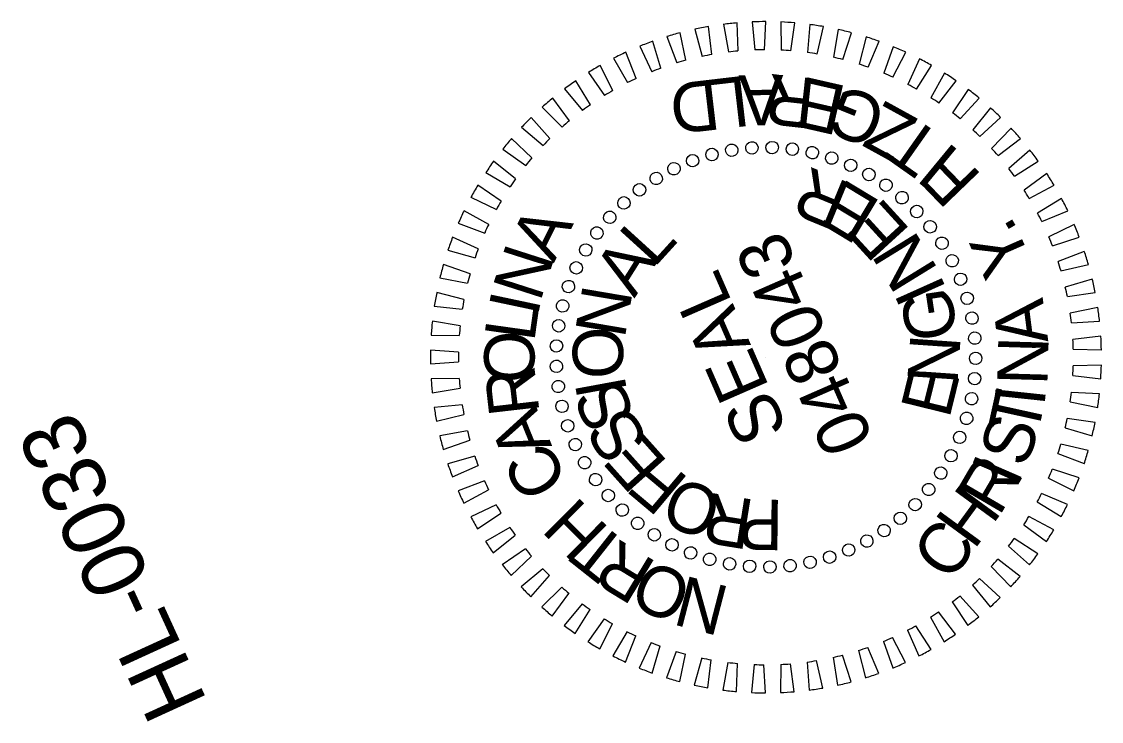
# Model space of a CAD drawing. Extents: x 2047210 to 2048779, y 758833 to 761037.
# Drawn here: x 2047247.5 to 2047376.2, y 760470.6 to 760554 of the extents above; entities that cross this region are included whole.
import ezdxf

# ---------------------------------------------------------------- set-up
doc = ezdxf.new("R2010")
doc.units = 0
doc.layers.add('Sheet Data Field CELL', color=7, linetype='Continuous')
doc.layers.add('Sheet PE Seal Cell', color=7, linetype='Continuous')

msp = doc.modelspace()

# ---------------------------------------------------------------- linework, layer by layer
at = {"layer": 'Sheet PE Seal Cell'}
for p, q in [((2047329.74, 760550.11), (2047329.34, 760553.44)), ((2047331.12, 760553.71), (2047331.72, 760550.41)), ((2047332.87, 760550.53), (2047332.76, 760553.88)), ((2047334.55, 760554), (2047334.87, 760550.66)), ((2047336.02, 760550.68), (2047336.2, 760554.03)), ((2047337.99, 760553.99), (2047338.02, 760550.64)), ((2047339.17, 760550.56), (2047339.63, 760553.88)), ((2047341.42, 760553.69), (2047341.16, 760550.34)), ((2047342.3, 760550.17), (2047343.05, 760553.44)), ((2047324.4, 760552.25), (2047325.56, 760549.1)), ((2047326.66, 760549.42), (2047325.98, 760552.71)), ((2047327.73, 760553.12), (2047328.61, 760549.89)), ((2047344.81, 760553.09), (2047344.26, 760549.78)), ((2047345.38, 760549.51), (2047346.41, 760552.71)), ((2047348.13, 760552.21), (2047347.31, 760548.96)), ((2047321.15, 760551.09), (2047322.58, 760548.06)), ((2047323.66, 760548.47), (2047322.7, 760551.68)), ((2047348.4, 760548.59), (2047349.7, 760551.69)), ((2047351.37, 760551.04), (2047350.27, 760547.87)), ((2047318.02, 760549.66), (2047319.71, 760546.76)), ((2047320.74, 760547.26), (2047319.51, 760550.38)), ((2047351.32, 760547.42), (2047352.88, 760550.39)), ((2047354.5, 760549.6), (2047353.12, 760546.54)), ((2047317.94, 760545.81), (2047316.45, 760548.81)), ((2047354.14, 760545.99), (2047355.95, 760548.82)), ((2047315.28, 760544.12), (2047313.53, 760546.99)), ((2047315.03, 760547.97), (2047316.95, 760545.22)), ((2047357.49, 760547.9), (2047355.86, 760544.96)), ((2047356.82, 760544.33), (2047358.86, 760546.99)), ((2047312.19, 760546.02), (2047314.34, 760543.45)), ((2047360.32, 760545.94), (2047358.44, 760543.16)), ((2047312.77, 760542.21), (2047310.78, 760544.92)), ((2047359.35, 760542.45), (2047361.61, 760544.92)), ((2047309.53, 760543.84), (2047311.9, 760541.47)), ((2047362.97, 760543.75), (2047360.86, 760541.14)), ((2047310.43, 760540.1), (2047308.22, 760542.62)), ((2047361.7, 760540.35), (2047364.18, 760542.62)), ((2047307.06, 760541.44), (2047309.63, 760539.28)), ((2047365.43, 760541.34), (2047363.1, 760538.92)), ((2047308.29, 760537.78), (2047305.86, 760540.11)), ((2047363.87, 760538.06), (2047366.53, 760540.11)), ((2047304.82, 760538.83), (2047307.56, 760536.9)), ((2047367.67, 760538.72), (2047365.14, 760536.51)), ((2047306.35, 760535.3), (2047303.74, 760537.4)), ((2047365.83, 760535.6), (2047368.66, 760537.41)), ((2047302.8, 760536.04), (2047305.7, 760534.35)), ((2047369.67, 760535.93), (2047366.97, 760533.94)), ((2047304.63, 760532.65), (2047301.85, 760534.52)), ((2047367.58, 760532.97), (2047370.55, 760534.53)), ((2047301.03, 760533.09), (2047304.06, 760531.65)), ((2047371.43, 760532.97), (2047368.57, 760531.22)), ((2047303.15, 760529.87), (2047300.21, 760531.5)), ((2047369.09, 760530.2), (2047372.18, 760531.5)), ((2047299.52, 760530), (2047302.67, 760528.83)), ((2047372.93, 760529.87), (2047369.92, 760528.38)), ((2047301.91, 760526.97), (2047298.84, 760528.34)), ((2047370.36, 760527.31), (2047373.55, 760528.34)), ((2047298.29, 760526.78), (2047301.52, 760525.89)), ((2047374.15, 760526.65), (2047371.03, 760525.43)), ((2047300.92, 760523.97), (2047297.75, 760525.07)), ((2047371.37, 760524.33), (2047374.64, 760525.08)), ((2047297.33, 760523.48), (2047300.63, 760522.86)), ((2047375.1, 760523.34), (2047371.88, 760522.39)), ((2047300.2, 760520.91), (2047296.95, 760521.73)), ((2047372.13, 760521.27), (2047375.45, 760521.73)), ((2047296.66, 760520.1), (2047300, 760519.77)), ((2047375.76, 760519.97), (2047372.47, 760519.29)), ((2047299.74, 760517.79), (2047296.43, 760518.32)), ((2047372.62, 760518.15), (2047375.97, 760518.33)), ((2047296.29, 760516.68), (2047299.64, 760516.64)), ((2047376.12, 760516.54), (2047372.79, 760516.15)), ((2047299.55, 760514.64), (2047296.21, 760514.89)), ((2047372.84, 760515), (2047376.19, 760514.9)), ((2047296.21, 760513.24), (2047299.55, 760513.49)), ((2047336.2, 760514.03), (2047336.2, 760514.03)), ((2047376.19, 760513.1), (2047372.83, 760513)), ((2047299.64, 760511.48), (2047296.28, 760511.45)), ((2047372.78, 760511.85), (2047376.12, 760511.45)), ((2047296.42, 760509.81), (2047299.74, 760510.34)), ((2047375.96, 760509.67), (2047372.61, 760509.85)), ((2047299.99, 760508.35), (2047296.65, 760508.03)), ((2047372.46, 760508.71), (2047375.75, 760508.03)), ((2047296.93, 760506.4), (2047300.19, 760507.22)), ((2047371.87, 760505.62), (2047375.08, 760504.65)), ((2047375.44, 760506.27), (2047372.12, 760506.74)), ((2047300.61, 760505.26), (2047297.31, 760504.65)), ((2047297.73, 760503.05), (2047300.91, 760504.15)), ((2047374.62, 760502.92), (2047371.36, 760503.68)), ((2047301.5, 760502.23), (2047298.27, 760501.34)), ((2047371.01, 760502.58), (2047374.13, 760501.35)), ((2047298.82, 760499.79), (2047301.89, 760501.15)), ((2047373.53, 760499.66), (2047370.34, 760500.69)), ((2047302.64, 760499.29), (2047299.5, 760498.13)), ((2047369.9, 760499.63), (2047372.9, 760498.13)), ((2047300.18, 760496.63), (2047303.12, 760498.25)), ((2047368.54, 760496.79), (2047371.4, 760495.04)), ((2047372.15, 760496.5), (2047369.06, 760497.81)), ((2047304.03, 760496.46), (2047301, 760495.03)), ((2047301.81, 760493.6), (2047304.6, 760495.46)), ((2047366.94, 760494.07), (2047369.64, 760492.08)), ((2047370.51, 760493.48), (2047367.55, 760495.04)), ((2047305.66, 760493.76), (2047302.76, 760492.08)), ((2047303.7, 760490.72), (2047306.31, 760492.82)), ((2047365.11, 760491.5), (2047367.63, 760489.29)), ((2047368.62, 760490.6), (2047365.8, 760492.42)), ((2047307.52, 760491.21), (2047304.77, 760489.28)), ((2047305.82, 760488.01), (2047308.25, 760490.33)), ((2047363.06, 760489.1), (2047365.38, 760486.68)), ((2047366.49, 760487.9), (2047363.83, 760489.96)), ((2047309.59, 760488.83), (2047307.02, 760486.67)), ((2047308.17, 760485.49), (2047310.39, 760488.01)), ((2047364.13, 760485.4), (2047361.66, 760487.67)), ((2047311.85, 760486.64), (2047309.48, 760484.27)), ((2047360.82, 760486.88), (2047362.92, 760484.27)), ((2047310.73, 760483.19), (2047312.72, 760485.89)), ((2047361.56, 760483.1), (2047359.3, 760485.58)), ((2047314.3, 760484.65), (2047312.14, 760482.08)), ((2047313.47, 760481.11), (2047315.23, 760483.97)), ((2047358.39, 760484.87), (2047360.27, 760482.08)), ((2047316.9, 760482.87), (2047314.97, 760480.13)), ((2047355.81, 760483.07), (2047357.43, 760480.13)), ((2047358.81, 760481.04), (2047356.77, 760483.7)), ((2047316.39, 760479.28), (2047317.89, 760482.28)), ((2047319.65, 760481.33), (2047317.96, 760478.43)), ((2047353.07, 760481.5), (2047354.44, 760478.43)), ((2047355.89, 760479.21), (2047354.08, 760482.04)), ((2047319.45, 760477.71), (2047320.69, 760480.83)), ((2047322.53, 760480.03), (2047321.09, 760476.99)), ((2047350.21, 760480.17), (2047351.31, 760477)), ((2047352.82, 760477.65), (2047351.27, 760480.62)), ((2047322.63, 760476.4), (2047323.6, 760479.62)), ((2047325.5, 760478.98), (2047324.33, 760475.83)), ((2047325.92, 760475.38), (2047326.6, 760478.66)), ((2047347.25, 760479.09), (2047348.07, 760475.83)), ((2047349.64, 760476.36), (2047348.34, 760479.45)), ((2047328.55, 760478.19), (2047327.66, 760474.95)), ((2047329.28, 760474.64), (2047329.68, 760477.97)), ((2047331.66, 760477.66), (2047331.05, 760474.36)), ((2047332.69, 760474.19), (2047332.81, 760477.54)), ((2047334.81, 760477.41), (2047334.48, 760474.07)), ((2047336.13, 760474.03), (2047335.95, 760477.38)), ((2047337.96, 760477.42), (2047337.92, 760474.07)), ((2047339.57, 760474.17), (2047339.11, 760477.5)), ((2047341.1, 760477.71), (2047341.35, 760474.37)), ((2047342.98, 760474.61), (2047342.24, 760477.88)), ((2047344.2, 760478.27), (2047344.74, 760474.96)), ((2047346.35, 760475.34), (2047345.32, 760478.54))]:
    msp.add_line(p, q, dxfattribs=at)
for radius, start, end in [(40, 99.8668, 102.2304), (40, 94.9353, 97.2989), (40, 90.0038, 92.3674), (40, 85.0722, 87.4359), (40, 80.1407, 82.5044), (40, 104.7983, 107.1619), (40, 75.2092, 77.5729), (40, 70.2777, 72.6413), (40, 109.7298, 112.0934), (36.65, 90.2866, 92.0845), (40, 65.3462, 67.7098), (40, 114.6613, 117.0249), (36.65, 105.0811, 106.879), (36.65, 100.1496, 101.9475), (36.65, 95.2181, 97.016), (36.65, 85.3551, 87.153), (36.65, 80.4236, 82.2215), (36.65, 75.4921, 77.29), (40, 60.4147, 62.7783), (40, 119.5928, 121.9564), (36.65, 110.0126, 111.8105), (36.65, 70.5606, 72.3585), (40, 124.5243, 126.8879), (36.65, 114.9442, 116.742), (36.65, 65.6291, 67.427), (40, 55.4832, 57.8468), (36.65, 119.8757, 121.6736), (36.65, 60.6976, 62.4955), (40, 50.5517, 52.9153), (40, 129.4558, 131.8194), (36.65, 55.7661, 57.564), (36.65, 124.8072, 126.6051), (36.65, 50.8346, 52.6325), (40, 45.6202, 47.9838), (40, 134.3873, 136.7509), (36.65, 129.7387, 131.5366), (36.65, 45.9031, 47.701), (40, 40.6887, 43.0523), (40, 139.3188, 141.6824), (36.65, 134.6702, 136.4681), (36.65, 139.6017, 141.3996), (36.65, 40.9716, 42.7694), (40, 35.7572, 38.1208), (40, 144.2503, 146.614), (36.65, 36.04, 37.8379), (36.65, 144.5332, 146.3311), (40, 30.8257, 33.1893), (40, 149.1818, 151.5455), (36.65, 31.1085, 32.9064), (36.65, 149.4647, 151.2626), (40, 25.8942, 28.2578), (40, 154.1133, 156.477), (36.65, 26.177, 27.9749), (36.65, 154.3962, 156.1941), (40, 20.9627, 23.3263), (40, 159.0449, 161.4085), (36.65, 21.2455, 23.0434), (36.65, 159.3277, 161.1256), (40, 16.0312, 18.3948), (40, 163.9764, 166.34), (36.65, 16.314, 18.1119), (36.65, 164.2592, 166.0571), (36.65, 11.3825, 13.1804), (40, 11.0996, 13.4633), (40, 168.9079, 171.2715), (36.65, 169.1907, 170.9886), (40, 6.1681, 8.5318), (36.65, 6.451, 8.2489), (40, 173.8394, 176.203), (36.65, 174.1222, 175.9201), (36.65, 1.5195, 3.3174), (40, 1.2366, 3.6003), (40, 178.7709, 181.1345), (36.65, 179.0537, 180.8516), (36.65, 356.588, 358.3859), (40, 356.3051, 358.6687), (40, 183.7024, 186.066), (36.65, 183.9852, 185.7831), (36.65, 351.6565, 353.4544), (40, 351.3736, 353.7372), (36.65, 188.9168, 190.7147), (40, 188.6339, 190.9975), (36.65, 346.725, 348.5229), (40, 346.4421, 348.8057), (40, 193.5654, 195.929), (36.65, 193.8483, 195.6462), (36.65, 341.7935, 343.5914), (36.65, 198.7798, 200.5777), (40, 341.5106, 343.8742), (40, 198.4969, 200.8605), (36.65, 336.862, 338.6599), (36.65, 203.7113, 205.5092), (40, 336.5791, 338.9427), (40, 203.4284, 205.792), (36.65, 331.9305, 333.7283), (36.65, 208.6428, 210.4407), (40, 331.6476, 334.0112), (40, 208.3599, 210.7235), (36.65, 326.9989, 328.7968), (36.65, 213.5743, 215.3722), (40, 326.7161, 329.0797), (40, 213.2914, 215.655), (36.65, 322.0674, 323.8653), (36.65, 218.5058, 220.3037), (40, 321.7846, 324.1482), (40, 218.2229, 220.5866), (36.65, 317.1359, 318.9338), (36.65, 223.4373, 225.2352), (36.65, 312.2044, 314.0023), (40, 316.8531, 319.2167), (40, 223.1544, 225.5181), (36.65, 228.3688, 230.1667), (36.65, 307.2729, 309.0708), (40, 311.9216, 314.2852), (40, 228.0859, 230.4496), (36.65, 233.3003, 235.0982), (36.65, 238.2318, 240.0297), (36.65, 302.3414, 304.1393), (40, 306.9901, 309.3537), (40, 233.0175, 235.3811), (36.65, 243.1633, 244.9612), (36.65, 297.4099, 299.2078), (40, 237.949, 240.3126), (36.65, 248.0948, 249.8927), (36.65, 292.4784, 294.2763), (40, 302.0586, 304.4222), (36.65, 253.0263, 254.8242), (36.65, 287.5469, 289.3448), (40, 297.127, 299.4907), (40, 242.8805, 245.2441), (36.65, 257.9579, 259.7557), (36.65, 262.8894, 264.6873), (36.65, 267.8209, 269.6188), (36.65, 272.7524, 274.5503), (36.65, 277.6839, 279.4818), (36.65, 282.6154, 284.4133), (40, 292.1955, 294.5592), (40, 247.812, 250.1756), (40, 287.264, 289.6276), (40, 252.7435, 255.1071), (40, 257.675, 260.0386), (40, 282.3325, 284.6961), (40, 262.6065, 264.9701), (40, 267.538, 269.9016), (40, 272.4695, 274.8331), (40, 277.401, 279.7646)]:
    msp.add_arc((2047336.2, 760514.03), radius, start, end, dxfattribs=at)
for centre, major_axis in [((2047332.12, 760538.7), (-0.172, 0.722)), ((2047334.52, 760538.98), (-0.101, 0.735)), ((2047336.94, 760539.02), (-0.03, 0.742)), ((2047339.35, 760538.83), (0.042, 0.741)), ((2047341.73, 760538.41), (0.113, 0.734)), ((2047327.46, 760537.46), (-0.307, 0.676)), ((2047329.76, 760538.19), (-0.241, 0.702)), ((2047344.05, 760537.77), (0.184, 0.719)), ((2047325.24, 760536.5), (-0.371, 0.643)), ((2047346.31, 760536.9), (0.252, 0.698)), ((2047348.47, 760535.81), (0.318, 0.671)), ((2047323.12, 760535.34), (-0.431, 0.604)), ((2047350.51, 760534.53), (0.382, 0.637)), ((2047321.13, 760533.98), (-0.488, 0.56)), ((2047319.27, 760532.43), (-0.539, 0.51)), ((2047352.42, 760533.05), (0.441, 0.597)), ((2047317.58, 760530.71), (-0.586, 0.456)), ((2047354.18, 760531.4), (0.497, 0.552)), ((2047355.78, 760529.58), (0.548, 0.501)), ((2047316.05, 760528.84), (-0.627, 0.397)), ((2047314.72, 760526.82), (-0.663, 0.334)), ((2047357.19, 760527.62), (0.593, 0.446)), ((2047358.4, 760525.53), (0.634, 0.387)), ((2047313.58, 760524.69), (-0.692, 0.269)), ((2047359.4, 760523.33), (0.668, 0.324)), ((2047312.66, 760522.46), (-0.715, 0.201)), ((2047360.19, 760521.05), (0.696, 0.258)), ((2047311.96, 760520.15), (-0.731, 0.131)), ((2047311.48, 760517.78), (-0.74, 0.06)), ((2047360.76, 760518.7), (0.718, 0.189)), ((2047311.23, 760515.38), (-0.742, -0.012)), ((2047361.09, 760516.31), (0.733, 0.119)), ((2047361.2, 760513.9), (0.741, 0.048)), ((2047311.22, 760512.96), (-0.738, -0.083)), ((2047361.07, 760511.48), (0.742, -0.024)), ((2047311.44, 760510.55), (-0.726, -0.154)), ((2047360.71, 760509.09), (0.736, -0.095)), ((2047311.89, 760508.18), (-0.708, -0.224)), ((2047360.12, 760506.75), (0.724, -0.166)), ((2047312.57, 760505.86), (-0.683, -0.291)), ((2047313.47, 760503.62), (-0.652, -0.355)), ((2047359.3, 760504.48), (0.704, -0.235)), ((2047358.27, 760502.29), (0.678, -0.302)), ((2047314.58, 760501.48), (-0.614, -0.417)), ((2047357.04, 760500.22), (0.646, -0.366)), ((2047315.89, 760499.45), (-0.571, -0.474)), ((2047317.4, 760497.56), (-0.523, -0.527)), ((2047355.6, 760498.27), (0.607, -0.427)), ((2047319.07, 760495.82), (-0.47, -0.575)), ((2047353.99, 760496.47), (0.563, -0.483)), ((2047352.22, 760494.84), (0.514, -0.535)), ((2047320.91, 760494.25), (-0.412, -0.618)), ((2047350.29, 760493.38), (0.46, -0.583)), ((2047322.89, 760492.87), (-0.35, -0.654)), ((2047348.23, 760492.12), (0.402, -0.624)), ((2047325, 760491.68), (-0.286, -0.685)), ((2047327.21, 760490.71), (-0.218, -0.71)), ((2047346.06, 760491.06), (0.34, -0.66)), ((2047329.5, 760489.95), (-0.149, -0.727)), ((2047331.86, 760489.41), (-0.078, -0.738)), ((2047341.46, 760489.59), (0.206, -0.713)), ((2047343.79, 760490.21), (0.274, -0.69)), ((2047334.25, 760489.11), (-0.006, -0.742)), ((2047336.67, 760489.04), (0.066, -0.739)), ((2047339.08, 760489.2), (0.137, -0.73))]:
    msp.add_ellipse(centre, major_axis=major_axis, ratio=0.999708, dxfattribs=at)

# ---------------------------------------------------------------- texts
at = {"layer": 'Sheet Data Field CELL'}
msp.add_text('HL-0033', height=7.5, rotation=114.5739, dxfattribs=at).set_placement((2047269.65, 760473))
at = {"layer": 'Sheet PE Seal Cell'}
for s, height, rotation, p in [('D', 6, 186.6623, (2047330.24, 760547.19)), ('L', 6, 186.6623, (2047333.74, 760547.6)), ('A', 6, 180.5461, (2047338.28, 760547.68)), ('R', 6, 173.7238, (2047342.27, 760547.2)), ('E', 6, 167.1492, (2047346.02, 760546.28)), ('G', 6, 158.1586, (2047350.94, 760544.35)), ('Z', 6, 151.1917, (2047354.51, 760542.34)), ('T', 6, 144.8236, (2047357.54, 760540.13)), ('I', 6, 140.4585, (2047359.46, 760538.43)), ('R', 6, 157.6079, (2047346.58, 760534.63)), ('F', 6, 133.9459, (2047362.08, 760535.63)), ('E', 6, 148.8549, (2047350.08, 760532.48)), ('E', 6, 132.4512, (2047353.56, 760529.11)), ('A', 6, 63.2869, (2047310.91, 760525.21)), ('.', 6, 120.7864, (2047366.32, 760529.17)), ('L', 6, 47.6989, (2047322.81, 760524.58)), ('N', 6, 121.602, (2047356.81, 760524.42)), ('048043', 6.185, 113.6102, (2047349.12, 760504.15)), ('Y', 6, 113.6749, (2047367.96, 760525.32)), ('N', 6, 72.2172, (2047309.27, 760520.51)), ('A', 6, 57.832, (2047320.52, 760521.01)), ('SEAL', 6.184, 113.6102, (2047338.85, 760505.38)), ('I', 6, 114.1525, (2047357.77, 760522.09)), ('I', 6, 78.0537, (2047308.98, 760518.8)), ('N', 6, 80.3523, (2047319.35, 760516.15)), ('G', 6, 98.5678, (2047359.07, 760516.47)), ('A', 6, 97.3045, (2047369.86, 760515.91)), ('L', 6, 82.0413, (2047308.57, 760515.76)), ('O', 6, 92.0658, (2047319.28, 760511.55)), ('O', 6, 89.2416, (2047308.57, 760510.91)), ('N', 6, 86.0381, (2047359.02, 760510.71)), ('N', 6, 88.3139, (2047369.74, 760510.63)), ('R', 6, 96.5309, (2047309.22, 760507.41)), ('E', 6, 76.1846, (2047358.04, 760506.59)), ('I', 6, 100.4557, (2047319.68, 760509.91)), ('S', 6, 114.6156, (2047320.77, 760507.01)), ('T', 6, 77.5807, (2047368.52, 760504.44)), ('I', 6, 83.9488, (2047369.38, 760508.08)), ('A', 6, 112.0181, (2047310.72, 760503.46)), ('S', 6, 122.9958, (2047322.43, 760504.03)), ('S', 6, 70.8616, (2047367.17, 760500.72)), ('E', 6, 131.7949, (2047324.64, 760501.46)), ('C', 6, 120.9025, (2047312.8, 760499.39)), ('R', 6, 59.6741, (2047364, 760494.96)), ('I', 6, 66.4965, (2047366.07, 760498.4)), ('F', 6, 140.0221, (2047327.16, 760499.47)), ('O', 6, 158.9698, (2047331.36, 760497.7)), ('H', 6, 53.8463, (2047361, 760490.97)), ('H', 6, 135.2714, (2047317.65, 760493.53)), ('R', 6, 170.8961, (2047335, 760497.01)), ('P', 6, 179.4033, (2047338.28, 760497.03)), ('C', 6, 53.8463, (2047358.15, 760487.07)), ('T', 6, 141.6645, (2047320.07, 760491.58)), ('R', 6, 148.7615, (2047323.36, 760489.51)), ('O', 6, 156.4241, (2047327.78, 760487.58)), ('N', 6, 165.4438, (2047332.07, 760486.59))]:
    msp.add_text(s, height=height, rotation=rotation, dxfattribs=at).set_placement(p)

doc.saveas('drawing.dxf')
